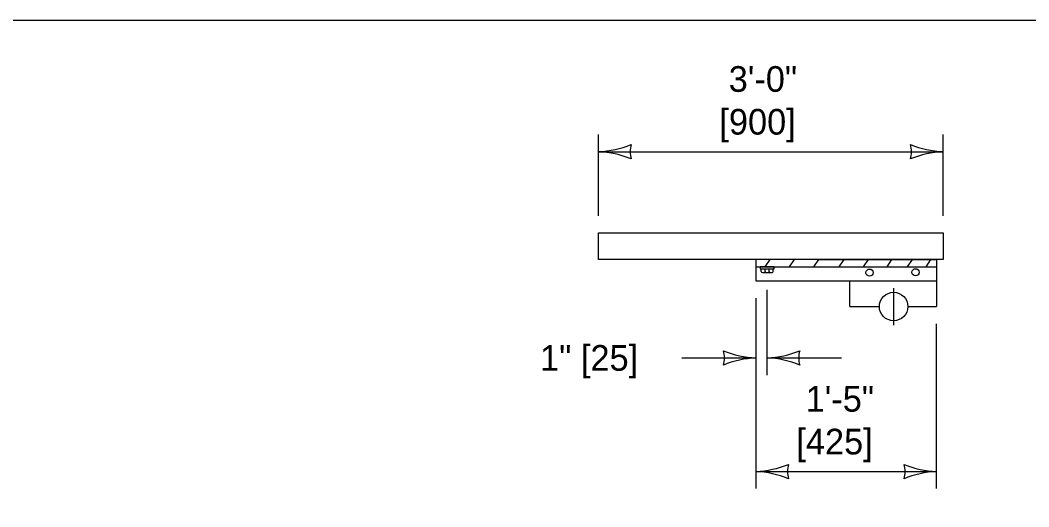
# Model space of a CAD drawing. Extents: x 49991.4 to 50021, y 49987.6 to 50011.4.
# Drawn here: x 50004.856 to 50007.212, y 49997.862 to 49998.999 of the extents above; entities that cross this region are included whole.
import ezdxf

# ---------------------------------------------------------------- set-up
doc = ezdxf.new("R2010")
doc.units = 0
for name, color, linetype in [('Level 1', 7, 'Continuous'), ('Level 2', 7, 'Continuous'), ('Level 3', 7, 'Continuous'), ('Level 5', 7, 'Continuous')]:
    doc.layers.add(name, color=color, linetype=linetype)

msp = doc.modelspace()

# ---------------------------------------------------------------- linework, layer by layer
at = {"layer": 'Level 1'}
for p, q in [((50006.2074, 49998.4396), (50006.2074, 49998.5017)), ((50006.2074, 49998.5017), (50007.0118, 49998.5017)), ((50007.0118, 49998.5017), (50007.0118, 49998.4396)), ((50007.0118, 49998.4396), (50006.2074, 49998.4396)), ((50006.5749, 49998.4396), (50006.5749, 49998.4228)), ((50006.5963, 49998.4228), (50006.6077, 49998.4396)), ((50006.6533, 49998.4228), (50006.6646, 49998.4396)), ((50006.7101, 49998.4228), (50006.7214, 49998.4396)), ((50006.7222, 49998.4396), (50006.929, 49998.4396)), ((50006.7693, 49998.4228), (50006.7806, 49998.4396)), ((50006.8261, 49998.4228), (50006.8374, 49998.4396)), ((50006.881, 49998.4228), (50006.8923, 49998.4396)), ((50006.929, 49998.4396), (50006.9968, 49998.4396)), ((50006.929, 49998.4228), (50006.9404, 49998.4396)), ((50006.9721, 49998.4228), (50006.9834, 49998.4396)), ((50006.9968, 49998.4396), (50006.9968, 49998.3297)), ((50006.5749, 49998.4228), (50006.8623, 49998.4228)), ((50006.5749, 49998.4228), (50006.5749, 49998.3896)), ((50006.5874, 49998.4118), (50006.5874, 49998.4181)), ((50006.59, 49998.4092), (50006.6126, 49998.4092)), ((50006.5966, 49998.4117), (50006.5966, 49998.4181)), ((50006.6058, 49998.4117), (50006.6058, 49998.4181)), ((50006.6151, 49998.4118), (50006.6151, 49998.4181)), ((50006.8623, 49998.4228), (50006.9968, 49998.4228)), ((50006.5749, 49998.3896), (50006.7941, 49998.3896)), ((50006.7941, 49998.3297), (50006.7941, 49998.3896)), ((50006.7941, 49998.3896), (50006.9968, 49998.3896)), ((50006.7941, 49998.3297), (50006.8631, 49998.3297)), ((50006.9287, 49998.3297), (50006.9968, 49998.3297))]:
    msp.add_line(p, q, dxfattribs=at)
for points in [[(49999.3835, 49998.9992), (50016.7501, 49998.9992), (50016.7501, 49987.7988), (49999.3835, 49987.7988)], [(50006.5847, 49998.4228), (50006.5847, 49998.4181), (50006.6175, 49998.4181), (50006.6175, 49998.4228)]]:
    msp.add_lwpolyline(points, close=True, dxfattribs=at)
for centre, radius in [((50006.8403, 49998.409), 0.00843), ((50006.9477, 49998.4098), 0.00843), ((50006.8964, 49998.3298), 0.0333)]:
    msp.add_circle(centre, radius, dxfattribs=at)
for centre, start, end in [((50006.59, 49998.4118), 180, 270), ((50006.5941, 49998.4118), 270, 0), ((50006.5992, 49998.4118), 180, 270), ((50006.6033, 49998.4118), 270, 0), ((50006.6084, 49998.4118), 180, 270), ((50006.6125, 49998.4118), 270, 0)]:
    msp.add_arc(centre, 0.00257, start, end, dxfattribs=at)
at = {"layer": 'Level 3'}
for p, q in [((50006.2074, 49998.5417), (50006.2074, 49998.7317)), ((50007.0118, 49998.5417), (50007.0118, 49998.7317)), ((50006.2074, 49998.6917), (50007.0118, 49998.6917)), ((50006.6013, 49998.1697), (50006.6013, 49998.3692)), ((50006.5749, 49998.3496), (50006.5749, 49997.9041)), ((50006.9968, 49997.9041), (50006.9968, 49998.2897)), ((50006.4015, 49998.2097), (50006.5749, 49998.2097)), ((50006.6013, 49998.2097), (50006.7747, 49998.2097)), ((50006.5754, 49997.9441), (50006.9968, 49997.9441))]:
    msp.add_line(p, q, dxfattribs=at)
for centre, radius, start, end in [((50006.1959, 49998.9244), 0.233, 272.8273, 292.0772), ((50006.1982, 49998.4696), 0.2223, 67.456, 87.6395), ((50006.3356, 49998.6917), 0.0548, 162.1388, 197.8612), ((50007.021, 49998.9139), 0.2223, 247.456, 267.6395), ((50006.8836, 49998.6917), 0.0548, 342.1388, 17.8612), ((50007.0233, 49998.459), 0.233, 92.8273, 112.0772), ((50006.5841, 49998.4319), 0.2223, 247.456, 267.6395), ((50006.4467, 49998.2097), 0.0548, 342.1388, 17.8612), ((50006.5898, 49998.4424), 0.233, 272.8273, 292.0772), ((50006.7295, 49998.2097), 0.0548, 162.1388, 197.8612), ((50006.5864, 49997.977), 0.233, 92.8273, 112.0772), ((50006.5921, 49997.9876), 0.2223, 67.456, 87.6395), ((50006.5634, 49998.1768), 0.233, 272.8273, 292.0772), ((50006.5657, 49997.722), 0.2223, 67.456, 87.6395), ((50006.7031, 49997.9441), 0.0548, 162.1388, 197.8612), ((50007.006, 49998.1662), 0.2223, 247.456, 267.6395), ((50006.8686, 49997.9441), 0.0548, 342.1388, 17.8612), ((50007.0083, 49997.7114), 0.233, 92.8273, 112.0772)]:
    msp.add_arc(centre, radius, start, end, dxfattribs=at)
at = {"layer": 'Level 5'}
msp.add_line((50006.8963, 49998.373), (50006.8963, 49998.2865), dxfattribs=at)

# ---------------------------------------------------------------- texts
at = {"layer": 'Level 2'}
for s, p in [('3\'-0"', (50006.5112, 49998.8317)), ('[900]', (50006.4894, 49998.7317)), ('1" [25]', (50006.0706, 49998.1797)), ('1\'-5"', (50006.6909, 49998.0841)), ('[425]', (50006.6692, 49997.9841))]:
    msp.add_text(s, height=0.06, dxfattribs=at).set_placement(p)

doc.saveas('drawing.dxf')
